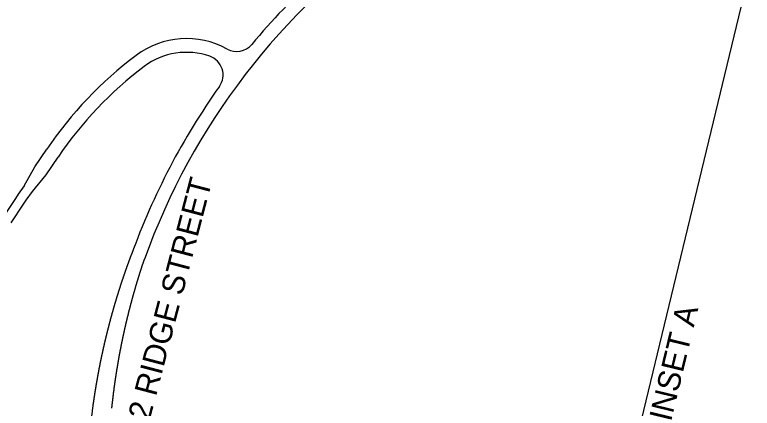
# Model space of a CAD drawing. Extents: x 1649669 to 1659218, y 588594 to 607900.
# Drawn here: x 1655108 to 1656826, y 604053 to 604969 of the extents above; entities that cross this region are included whole.
import ezdxf

# ---------------------------------------------------------------- set-up
doc = ezdxf.new("R2010")
doc.units = 0
for name, color, linetype in [('CTL Sheet Notes CELL', 7, 'Continuous'), ('Exist Roads EOP', 7, 'Continuous'), ('Sheet Data Field CELL', 7, 'Continuous')]:
    doc.layers.add(name, color=color, linetype=linetype)

msp = doc.modelspace()

# ---------------------------------------------------------------- linework, layer by layer
at = {"layer": 'CTL Sheet Notes CELL'}
msp.add_lwpolyline([(1656065.2, 601942.6), (1657135.7, 606376.1), (1658875.8, 605955.9), (1657805.4, 601522.5)], close=True, dxfattribs=at)
at = {"layer": 'Exist Roads EOP'}
for p, q in [((1655154.7, 604614.7), (1655182.6, 604655.9)), ((1655181, 604596.6), (1655209.1, 604637.9)), ((1655129.9, 604571), (1655154.7, 604614.7)), ((1655149.7, 604557.5), (1655181, 604596.6)), ((1655109.6, 604541.2), (1655080.1, 604497.4)), ((1655099.5, 604484.4), (1655128.7, 604528.2))]:
    msp.add_line(p, q, dxfattribs=at)
for points in [[(1655129.9, 604571), (1655116.3, 604551.2), (1655109.6, 604541.2)], [(1655128.7, 604528.2), (1655134.8, 604537.2), (1655149.7, 604557.5)]]:
    msp.add_lwpolyline(points, dxfattribs=at)
for centre, radius, start, end in [((1656901, 603864.5), 1616, 124.6758, 140.1492), ((1656901, 603864.5), 1584, 124.6758, 160.233), ((1655508.3, 604717.5), 196, 61.1591, 126.9127), ((1655625.1, 604929.5), 46, 241.1591, 320.1492), ((1655940.7, 604141.8), 916, 126.9127, 145.8608), ((1655508.3, 604717.5), 164, 70.6651, 126.9127), ((1655547.4, 604828.8), 46, 324.5327, 70.6651), ((1655547.4, 604828.8), 46, 324.5327, 70.6651), ((1655940.7, 604141.8), 884, 126.9127, 145.8608), ((1656901, 603864.5), 1616, 144.5327, 160.233)]:
    msp.add_arc(centre, radius, start, end, dxfattribs=at)
for points in [[(1655356, 604342.4), (1655356.3, 604343.3), (1655356.6, 604344.3), (1655356.9, 604345.2), (1655357.3, 604346.1), (1655357.6, 604347.1), (1655357.9, 604348), (1655358.2, 604348.9), (1655358.5, 604349.9), (1655358.8, 604350.8), (1655359.1, 604351.7), (1655359.4, 604352.7), (1655359.7, 604353.6), (1655360.1, 604354.5), (1655360.4, 604355.5), (1655360.7, 604356.4), (1655361, 604357.3), (1655361.3, 604358.3), (1655361.6, 604359.2), (1655361.9, 604360.1), (1655362.3, 604361), (1655362.6, 604362), (1655362.9, 604362.9), (1655363.2, 604363.8), (1655363.5, 604364.8), (1655363.9, 604365.7), (1655364.2, 604366.6), (1655364.5, 604367.6), (1655364.8, 604368.5), (1655365.1, 604369.4), (1655365.5, 604370.3), (1655365.8, 604371.3), (1655366.1, 604372.2), (1655366.4, 604373.1), (1655366.8, 604374.1), (1655367.1, 604375), (1655367.4, 604375.9), (1655367.7, 604376.8), (1655368.1, 604377.8), (1655368.4, 604378.7), (1655368.7, 604379.6), (1655369.1, 604380.5), (1655369.4, 604381.5), (1655369.7, 604382.4), (1655370, 604383.3), (1655370.4, 604384.2), (1655370.7, 604385.2), (1655371, 604386.1), (1655371.4, 604387), (1655371.7, 604388), (1655372, 604388.9), (1655372.4, 604389.8), (1655372.7, 604390.7), (1655373, 604391.6), (1655373.4, 604392.6), (1655373.7, 604393.5), (1655374.1, 604394.4), (1655374.4, 604395.3), (1655374.7, 604396.3), (1655375.1, 604397.2), (1655375.4, 604398.1), (1655375.7, 604399), (1655376.1, 604400), (1655376.4, 604400.9), (1655376.8, 604401.8), (1655377.1, 604402.7), (1655377.5, 604403.6), (1655377.8, 604404.6), (1655378.1, 604405.5), (1655378.5, 604406.4), (1655378.8, 604407.3), (1655379.2, 604408.2), (1655379.5, 604409.2), (1655380.2, 604411)], [(1655388.9, 604332.2), (1655389.2, 604333.1), (1655389.4, 604334.1), (1655389.7, 604335), (1655390, 604335.9), (1655390.2, 604336.8), (1655390.5, 604337.8), (1655390.8, 604338.7), (1655391.1, 604339.6), (1655391.3, 604340.5), (1655391.6, 604341.5), (1655391.9, 604342.4), (1655392.2, 604343.3), (1655392.4, 604344.2), (1655392.7, 604345.1), (1655393, 604346.1), (1655393.3, 604347), (1655393.5, 604347.9), (1655393.8, 604348.8), (1655394.1, 604349.8), (1655394.4, 604350.7), (1655394.7, 604351.6), (1655394.9, 604352.5), (1655395.2, 604353.4), (1655395.5, 604354.4), (1655395.8, 604355.3), (1655396.1, 604356.2), (1655396.4, 604357.1), (1655396.6, 604358), (1655396.9, 604359), (1655397.2, 604359.9), (1655397.5, 604360.8), (1655397.8, 604361.7), (1655398.1, 604362.6), (1655398.4, 604363.6), (1655398.6, 604364.5), (1655398.9, 604365.4), (1655399.2, 604366.3), (1655399.5, 604367.2), (1655399.8, 604368.2), (1655400.1, 604369.1), (1655400.4, 604370), (1655400.7, 604370.9), (1655401, 604371.8), (1655401.3, 604372.7), (1655401.6, 604373.7), (1655401.9, 604374.6), (1655402.2, 604375.5), (1655402.4, 604376.4), (1655402.7, 604377.3), (1655403, 604378.2), (1655403.3, 604379.2), (1655403.6, 604380.1), (1655403.9, 604381), (1655404.2, 604381.9), (1655404.5, 604382.8), (1655404.8, 604383.7), (1655405.1, 604384.6), (1655405.4, 604385.6), (1655405.7, 604386.5), (1655406, 604387.4), (1655406.3, 604388.3), (1655406.6, 604389.2), (1655407, 604390.1), (1655407.3, 604391.1), (1655407.6, 604392), (1655407.9, 604392.9), (1655408.2, 604393.8), (1655408.5, 604394.7), (1655408.8, 604395.6), (1655409.1, 604396.5), (1655409.4, 604397.4), (1655409.7, 604398.4), (1655410.3, 604400.2)], [(1655334.9, 604272.7), (1655335.2, 604273.7), (1655335.5, 604274.6), (1655335.7, 604275.6), (1655336, 604276.5), (1655336.3, 604277.4), (1655336.5, 604278.4), (1655336.8, 604279.3), (1655337.1, 604280.3), (1655337.3, 604281.2), (1655337.6, 604282.2), (1655337.9, 604283.1), (1655338.1, 604284.1), (1655338.4, 604285), (1655338.7, 604286), (1655339, 604286.9), (1655339.2, 604287.9), (1655339.5, 604288.8), (1655339.8, 604289.7), (1655340, 604290.7), (1655340.3, 604291.6), (1655340.6, 604292.6), (1655340.9, 604293.5), (1655341.2, 604294.5), (1655341.4, 604295.4), (1655341.7, 604296.4), (1655342, 604297.3), (1655342.3, 604298.2), (1655342.5, 604299.2), (1655342.8, 604300.1), (1655343.1, 604301.1), (1655343.4, 604302), (1655343.7, 604303), (1655344, 604303.9), (1655344.2, 604304.8), (1655344.5, 604305.8), (1655344.8, 604306.7), (1655345.1, 604307.7), (1655345.4, 604308.6), (1655345.7, 604309.6), (1655345.9, 604310.5), (1655346.2, 604311.4), (1655346.5, 604312.4), (1655346.8, 604313.3), (1655347.1, 604314.3), (1655347.4, 604315.2), (1655347.7, 604316.1), (1655348, 604317.1), (1655348.3, 604318), (1655348.6, 604319), (1655348.8, 604319.9), (1655349.1, 604320.8), (1655349.4, 604321.8), (1655349.7, 604322.7), (1655350, 604323.7), (1655350.3, 604324.6), (1655350.6, 604325.5), (1655350.9, 604326.5), (1655351.2, 604327.4), (1655351.5, 604328.3), (1655351.8, 604329.3), (1655352.1, 604330.2), (1655352.4, 604331.2), (1655352.7, 604332.1), (1655353, 604333), (1655353.3, 604334), (1655353.6, 604334.9), (1655353.9, 604335.8), (1655354.2, 604336.8), (1655354.5, 604337.7), (1655354.8, 604338.6), (1655355.1, 604339.6), (1655355.4, 604340.5), (1655355.7, 604341.5), (1655356, 604342.4)], [(1655370.5, 604263.4), (1655370.8, 604264.4), (1655371, 604265.3), (1655371.2, 604266.2), (1655371.5, 604267.2), (1655371.7, 604268.1), (1655371.9, 604269), (1655372.1, 604270), (1655372.4, 604270.9), (1655372.6, 604271.8), (1655372.8, 604272.8), (1655373.1, 604273.7), (1655373.3, 604274.6), (1655373.5, 604275.6), (1655373.8, 604276.5), (1655374, 604277.4), (1655374.2, 604278.4), (1655374.5, 604279.3), (1655374.7, 604280.2), (1655375, 604281.2), (1655375.2, 604282.1), (1655375.4, 604283), (1655375.7, 604284), (1655375.9, 604284.9), (1655376.2, 604285.8), (1655376.4, 604286.8), (1655376.6, 604287.7), (1655376.9, 604288.6), (1655377.1, 604289.5), (1655377.4, 604290.5), (1655377.6, 604291.4), (1655377.8, 604292.3), (1655378.1, 604293.3), (1655378.3, 604294.2), (1655378.6, 604295.1), (1655378.8, 604296.1), (1655379.1, 604297), (1655379.3, 604297.9), (1655379.6, 604298.9), (1655379.8, 604299.8), (1655380.1, 604300.7), (1655380.3, 604301.6), (1655380.6, 604302.6), (1655380.8, 604303.5), (1655381.1, 604304.4), (1655381.3, 604305.4), (1655381.6, 604306.3), (1655381.8, 604307.2), (1655382.1, 604308.1), (1655382.3, 604309.1), (1655382.6, 604310), (1655382.9, 604310.9), (1655383.1, 604311.9), (1655383.4, 604312.8), (1655383.6, 604313.7), (1655383.9, 604314.6), (1655384.1, 604315.6), (1655384.4, 604316.5), (1655384.7, 604317.4), (1655384.9, 604318.3), (1655385.2, 604319.3), (1655385.4, 604320.2), (1655385.7, 604321.1), (1655386, 604322), (1655386.2, 604323), (1655386.5, 604323.9), (1655386.8, 604324.8), (1655387, 604325.8), (1655387.3, 604326.7), (1655387.6, 604327.6), (1655387.8, 604328.5), (1655388.1, 604329.5), (1655388.4, 604330.4), (1655388.6, 604331.3), (1655388.9, 604332.2)], [(1655317, 604202.1), (1655317.2, 604203.1), (1655317.4, 604204), (1655317.6, 604205), (1655317.9, 604205.9), (1655318.1, 604206.9), (1655318.3, 604207.9), (1655318.5, 604208.8), (1655318.8, 604209.8), (1655319, 604210.7), (1655319.2, 604211.7), (1655319.4, 604212.6), (1655319.7, 604213.6), (1655319.9, 604214.6), (1655320.1, 604215.5), (1655320.4, 604216.5), (1655320.6, 604217.4), (1655320.8, 604218.4), (1655321.1, 604219.4), (1655321.3, 604220.3), (1655321.5, 604221.3), (1655321.8, 604222.2), (1655322, 604223.2), (1655322.2, 604224.1), (1655322.5, 604225.1), (1655322.7, 604226), (1655322.9, 604227), (1655323.2, 604228), (1655323.4, 604228.9), (1655323.6, 604229.9), (1655323.9, 604230.8), (1655324.1, 604231.8), (1655324.4, 604232.7), (1655324.6, 604233.7), (1655324.8, 604234.6), (1655325.1, 604235.6), (1655325.3, 604236.6), (1655325.6, 604237.5), (1655325.8, 604238.5), (1655326, 604239.4), (1655326.3, 604240.4), (1655326.5, 604241.3), (1655326.8, 604242.3), (1655327, 604243.2), (1655327.3, 604244.2), (1655327.5, 604245.1), (1655327.8, 604246.1), (1655328, 604247), (1655328.3, 604248), (1655328.5, 604249), (1655328.8, 604249.9), (1655329, 604250.9), (1655329.3, 604251.8), (1655329.5, 604252.8), (1655329.8, 604253.7), (1655330, 604254.7), (1655330.3, 604255.6), (1655330.5, 604256.6), (1655330.8, 604257.5), (1655331, 604258.5), (1655331.3, 604259.4), (1655331.5, 604260.4), (1655331.8, 604261.3), (1655332.1, 604262.3), (1655332.3, 604263.2), (1655332.6, 604264.2), (1655332.8, 604265.1), (1655333.1, 604266.1), (1655333.4, 604267), (1655333.6, 604268), (1655333.9, 604268.9), (1655334.1, 604269.9), (1655334.4, 604270.8), (1655334.7, 604271.8), (1655334.9, 604272.7)], [(1655355.3, 604193.9), (1655355.5, 604194.9), (1655355.7, 604195.8), (1655355.9, 604196.8), (1655356.1, 604197.7), (1655356.2, 604198.6), (1655356.4, 604199.6), (1655356.6, 604200.5), (1655356.8, 604201.5), (1655357, 604202.4), (1655357.2, 604203.4), (1655357.4, 604204.3), (1655357.6, 604205.2), (1655357.8, 604206.2), (1655358, 604207.1), (1655358.1, 604208.1), (1655358.3, 604209), (1655358.5, 604209.9), (1655358.7, 604210.9), (1655358.9, 604211.8), (1655359.1, 604212.8), (1655359.3, 604213.7), (1655359.5, 604214.7), (1655359.7, 604215.6), (1655359.9, 604216.5), (1655360.1, 604217.5), (1655360.3, 604218.4), (1655360.5, 604219.4), (1655360.7, 604220.3), (1655360.9, 604221.2), (1655361.1, 604222.2), (1655361.3, 604223.1), (1655361.5, 604224.1), (1655361.7, 604225), (1655361.9, 604225.9), (1655362.1, 604226.9), (1655362.3, 604227.8), (1655362.5, 604228.8), (1655362.7, 604229.7), (1655362.9, 604230.6), (1655363.2, 604231.6), (1655363.4, 604232.5), (1655363.6, 604233.4), (1655363.8, 604234.4), (1655364, 604235.3), (1655364.2, 604236.3), (1655364.4, 604237.2), (1655364.6, 604238.1), (1655364.8, 604239.1), (1655365, 604240), (1655365.3, 604241), (1655365.5, 604241.9), (1655365.7, 604242.8), (1655365.9, 604243.8), (1655366.1, 604244.7), (1655366.3, 604245.6), (1655366.5, 604246.6), (1655366.8, 604247.5), (1655367, 604248.5), (1655367.2, 604249.4), (1655367.4, 604250.3), (1655367.6, 604251.3), (1655367.9, 604252.2), (1655368.1, 604253.1), (1655368.3, 604254.1), (1655368.5, 604255), (1655368.7, 604255.9), (1655369, 604256.9), (1655369.2, 604257.8), (1655369.4, 604258.8), (1655369.6, 604259.7), (1655369.9, 604260.6), (1655370.1, 604261.6), (1655370.3, 604262.5), (1655370.5, 604263.4)], [(1655302.2, 604130.7), (1655302.4, 604131.7), (1655302.6, 604132.6), (1655302.7, 604133.6), (1655302.9, 604134.6), (1655303.1, 604135.5), (1655303.3, 604136.5), (1655303.5, 604137.5), (1655303.7, 604138.4), (1655303.8, 604139.4), (1655304, 604140.4), (1655304.2, 604141.4), (1655304.4, 604142.3), (1655304.6, 604143.3), (1655304.8, 604144.3), (1655304.9, 604145.2), (1655305.1, 604146.2), (1655305.3, 604147.2), (1655305.5, 604148.1), (1655305.7, 604149.1), (1655305.9, 604150.1), (1655306.1, 604151), (1655306.3, 604152), (1655306.5, 604153), (1655306.6, 604153.9), (1655306.8, 604154.9), (1655307, 604155.9), (1655307.2, 604156.8), (1655307.4, 604157.8), (1655307.6, 604158.8), (1655307.8, 604159.7), (1655308, 604160.7), (1655308.2, 604161.7), (1655308.4, 604162.6), (1655308.6, 604163.6), (1655308.8, 604164.6), (1655309, 604165.5), (1655309.2, 604166.5), (1655309.4, 604167.5), (1655309.6, 604168.4), (1655309.8, 604169.4), (1655310, 604170.3), (1655310.2, 604171.3), (1655310.4, 604172.3), (1655310.6, 604173.2), (1655310.8, 604174.2), (1655311, 604175.2), (1655311.2, 604176.1), (1655311.4, 604177.1), (1655311.6, 604178.1), (1655311.8, 604179), (1655312, 604180), (1655312.3, 604180.9), (1655312.5, 604181.9), (1655312.7, 604182.9), (1655312.9, 604183.8), (1655313.1, 604184.8), (1655313.3, 604185.8), (1655313.5, 604186.7), (1655313.7, 604187.7), (1655313.9, 604188.6), (1655314.2, 604189.6), (1655314.4, 604190.6), (1655314.6, 604191.5), (1655314.8, 604192.5), (1655315, 604193.5), (1655315.2, 604194.4), (1655315.4, 604195.4), (1655315.7, 604196.3), (1655315.9, 604197.3), (1655316.1, 604198.3), (1655316.3, 604199.2), (1655316.5, 604200.2), (1655316.8, 604201.1), (1655317, 604202.1)], [(1655343.2, 604123.9), (1655343.4, 604124.8), (1655343.5, 604125.8), (1655343.7, 604126.7), (1655343.8, 604127.7), (1655344, 604128.6), (1655344.1, 604129.6), (1655344.3, 604130.5), (1655344.4, 604131.5), (1655344.5, 604132.4), (1655344.7, 604133.4), (1655344.8, 604134.3), (1655345, 604135.3), (1655345.1, 604136.2), (1655345.3, 604137.2), (1655345.4, 604138.1), (1655345.6, 604139.1), (1655345.7, 604140), (1655345.9, 604140.9), (1655346, 604141.9), (1655346.2, 604142.8), (1655346.3, 604143.8), (1655346.5, 604144.7), (1655346.7, 604145.7), (1655346.8, 604146.6), (1655347, 604147.6), (1655347.1, 604148.5), (1655347.3, 604149.5), (1655347.4, 604150.4), (1655347.6, 604151.4), (1655347.8, 604152.3), (1655347.9, 604153.3), (1655348.1, 604154.2), (1655348.2, 604155.2), (1655348.4, 604156.1), (1655348.6, 604157.1), (1655348.7, 604158), (1655348.9, 604159), (1655349, 604159.9), (1655349.2, 604160.8), (1655349.4, 604161.8), (1655349.5, 604162.7), (1655349.7, 604163.7), (1655349.9, 604164.6), (1655350, 604165.6), (1655350.2, 604166.5), (1655350.4, 604167.5), (1655350.5, 604168.4), (1655350.7, 604169.4), (1655350.9, 604170.3), (1655351.1, 604171.3), (1655351.2, 604172.2), (1655351.4, 604173.1), (1655351.6, 604174.1), (1655351.7, 604175), (1655351.9, 604176), (1655352.1, 604176.9), (1655352.3, 604177.9), (1655352.4, 604178.8), (1655352.6, 604179.8), (1655352.8, 604180.7), (1655353, 604181.7), (1655353.1, 604182.6), (1655353.3, 604183.5), (1655353.5, 604184.5), (1655353.7, 604185.4), (1655353.9, 604186.4), (1655354, 604187.3), (1655354.2, 604188.3), (1655354.4, 604189.2), (1655354.6, 604190.2), (1655354.8, 604191.1), (1655354.9, 604192), (1655355.1, 604193), (1655355.3, 604193.9)], [(1655290.6, 604058.7), (1655290.7, 604059.7), (1655290.9, 604060.7), (1655291, 604061.7), (1655291.1, 604062.6), (1655291.3, 604063.6), (1655291.4, 604064.6), (1655291.6, 604065.6), (1655291.7, 604066.5), (1655291.9, 604067.5), (1655292, 604068.5), (1655292.1, 604069.5), (1655292.3, 604070.4), (1655292.4, 604071.4), (1655292.6, 604072.4), (1655292.7, 604073.4), (1655292.9, 604074.3), (1655293, 604075.3), (1655293.2, 604076.3), (1655293.3, 604077.2), (1655293.4, 604078.2), (1655293.6, 604079.2), (1655293.7, 604080.2), (1655293.9, 604081.1), (1655294, 604082.1), (1655294.2, 604083.1), (1655294.3, 604084.1), (1655294.5, 604085), (1655294.6, 604086), (1655294.8, 604087), (1655294.9, 604087.9), (1655295.1, 604088.9), (1655295.3, 604089.9), (1655295.4, 604090.9), (1655295.6, 604091.8), (1655295.7, 604092.8), (1655295.9, 604093.8), (1655296, 604094.8), (1655296.2, 604095.7), (1655296.3, 604096.7), (1655296.5, 604097.7), (1655296.7, 604098.6), (1655296.8, 604099.6), (1655297, 604100.6), (1655297.1, 604101.6), (1655297.3, 604102.5), (1655297.5, 604103.5), (1655297.6, 604104.5), (1655297.8, 604105.5), (1655297.9, 604106.4), (1655298.1, 604107.4), (1655298.3, 604108.4), (1655298.4, 604109.3), (1655298.6, 604110.3), (1655298.8, 604111.3), (1655298.9, 604112.3), (1655299.1, 604113.2), (1655299.3, 604114.2), (1655299.4, 604115.2), (1655299.6, 604116.1), (1655299.8, 604117.1), (1655299.9, 604118.1), (1655300.1, 604119.1), (1655300.3, 604120), (1655300.5, 604121), (1655300.6, 604122), (1655300.8, 604122.9), (1655301, 604123.9), (1655301.2, 604124.9), (1655301.3, 604125.8), (1655301.5, 604126.8), (1655301.7, 604127.8), (1655301.9, 604128.8), (1655302, 604129.7), (1655302.2, 604130.7)], [(1655334.3, 604053.3), (1655334.4, 604054.3), (1655334.5, 604055.2), (1655334.6, 604056.2), (1655334.7, 604057.1), (1655334.8, 604058.1), (1655334.9, 604059), (1655335, 604060), (1655335.1, 604061), (1655335.2, 604061.9), (1655335.3, 604062.9), (1655335.4, 604063.8), (1655335.5, 604064.8), (1655335.6, 604065.7), (1655335.7, 604066.7), (1655335.9, 604067.7), (1655336, 604068.6), (1655336.1, 604069.6), (1655336.2, 604070.5), (1655336.3, 604071.5), (1655336.4, 604072.4), (1655336.5, 604073.4), (1655336.6, 604074.3), (1655336.7, 604075.3), (1655336.9, 604076.2), (1655337, 604077.2), (1655337.1, 604078.2), (1655337.2, 604079.1), (1655337.3, 604080.1), (1655337.4, 604081), (1655337.6, 604082), (1655337.7, 604082.9), (1655337.8, 604083.9), (1655337.9, 604084.8), (1655338, 604085.8), (1655338.1, 604086.7), (1655338.3, 604087.7), (1655338.4, 604088.7), (1655338.5, 604089.6), (1655338.6, 604090.6), (1655338.8, 604091.5), (1655338.9, 604092.5), (1655339, 604093.4), (1655339.1, 604094.4), (1655339.3, 604095.3), (1655339.4, 604096.3), (1655339.5, 604097.2), (1655339.6, 604098.2), (1655339.8, 604099.1), (1655339.9, 604100.1), (1655340, 604101), (1655340.1, 604102), (1655340.3, 604102.9), (1655340.4, 604103.9), (1655340.5, 604104.8), (1655340.7, 604105.8), (1655340.8, 604106.8), (1655340.9, 604107.7), (1655341.1, 604108.7), (1655341.2, 604109.6), (1655341.3, 604110.6), (1655341.5, 604111.5), (1655341.6, 604112.5), (1655341.7, 604113.4), (1655341.9, 604114.4), (1655342, 604115.3), (1655342.1, 604116.3), (1655342.3, 604117.2), (1655342.4, 604118.2), (1655342.5, 604119.1), (1655342.7, 604120.1), (1655342.8, 604121), (1655343, 604122), (1655343.1, 604122.9), (1655343.2, 604123.9)], [(1655271.2, 603837.9), (1655271.4, 603841.6), (1655271.7, 603845.4), (1655271.9, 603849.2), (1655272.2, 603853), (1655272.5, 603856.8), (1655272.7, 603860.5), (1655273, 603864.3), (1655273.3, 603868.1), (1655273.5, 603871.9), (1655273.8, 603875.7), (1655274.1, 603879.4), (1655274.4, 603883.2), (1655274.6, 603887), (1655274.9, 603890.8), (1655275.2, 603894.6), (1655275.5, 603898.3), (1655275.7, 603902.1), (1655276, 603905.9), (1655276.3, 603909.7), (1655276.6, 603913.5), (1655276.9, 603917.3), (1655277.2, 603921.1), (1655277.5, 603924.9), (1655277.8, 603928.6), (1655278.1, 603932.4), (1655278.4, 603936.2), (1655278.7, 603940), (1655279, 603943.8), (1655279.3, 603947.6), (1655279.6, 603951.4), (1655279.9, 603955.2), (1655280.3, 603959), (1655280.6, 603962.8), (1655280.9, 603966.6), (1655281.3, 603970.3), (1655281.6, 603974.1), (1655282, 603977.9), (1655282.3, 603981.7), (1655282.7, 603985.5), (1655283, 603989.3), (1655283.4, 603993.1), (1655283.8, 603996.9), (1655284.1, 604000.7), (1655284.5, 604004.5), (1655284.9, 604008.3), (1655285.3, 604012.1), (1655285.7, 604015.9), (1655286.1, 604019.7), (1655286.5, 604023.5), (1655286.9, 604027.3), (1655287.3, 604031.1), (1655287.8, 604034.9), (1655288.2, 604038.7), (1655288.6, 604042.5), (1655289.1, 604046.3), (1655289.5, 604050), (1655290, 604053.8), (1655290.5, 604057.6), (1655290.6, 604058.7)]]:
    msp.add_spline(points, degree=3, dxfattribs=at)

# ---------------------------------------------------------------- texts
at = {"layer": 'CTL Sheet Notes CELL'}
msp.add_text('INSET A', height=52.5, rotation=76.4261, dxfattribs=at).set_placement((1656636.9, 604020.4))
at = {"layer": 'Sheet Data Field CELL'}
msp.add_text('SR 1542 RIDGE STREET', height=52.501, rotation=75.3466, dxfattribs=at).set_placement((1655362.9, 603796.2))

doc.saveas('drawing.dxf')
